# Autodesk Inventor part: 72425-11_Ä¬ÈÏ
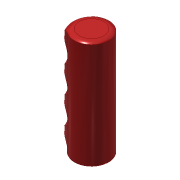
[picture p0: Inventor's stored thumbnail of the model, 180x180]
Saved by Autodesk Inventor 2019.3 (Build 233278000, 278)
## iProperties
Created: 2010-06
Part Number: 72425-11_Ä¬ÈÏ
Material: Ogólny
Document SubType Name: Modeling
Designer: CADENGINEERING4
Density: 1 g/cm^3
Appearance: Jasnoczerwona
Author: CADENGINEERING4
Revision Number: ÈÎºÎ
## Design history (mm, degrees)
feature "NONE"
node "Bryła1"
